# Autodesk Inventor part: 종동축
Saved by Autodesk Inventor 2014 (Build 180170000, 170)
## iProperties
Created: 2026-05
Part Number: 종동축
Material: 강철, 탄소
Document SubType Name: Modeling
Designer: dg
Density: 7.87 g/cm^3
Appearance: 반연마
Mass: 889.736 g
Surface Area: 209.526 cm^2
Volume: 113.054 cm^3
Author: jhkim
Creation Date: 2026-04-23
Sending System: Autodesk Inventor 2027
Preprocessor: ST-DEVELOPER v20.1
Author: dg
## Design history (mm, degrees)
node "종동축1"
node "솔리드1"
node "기준1"
